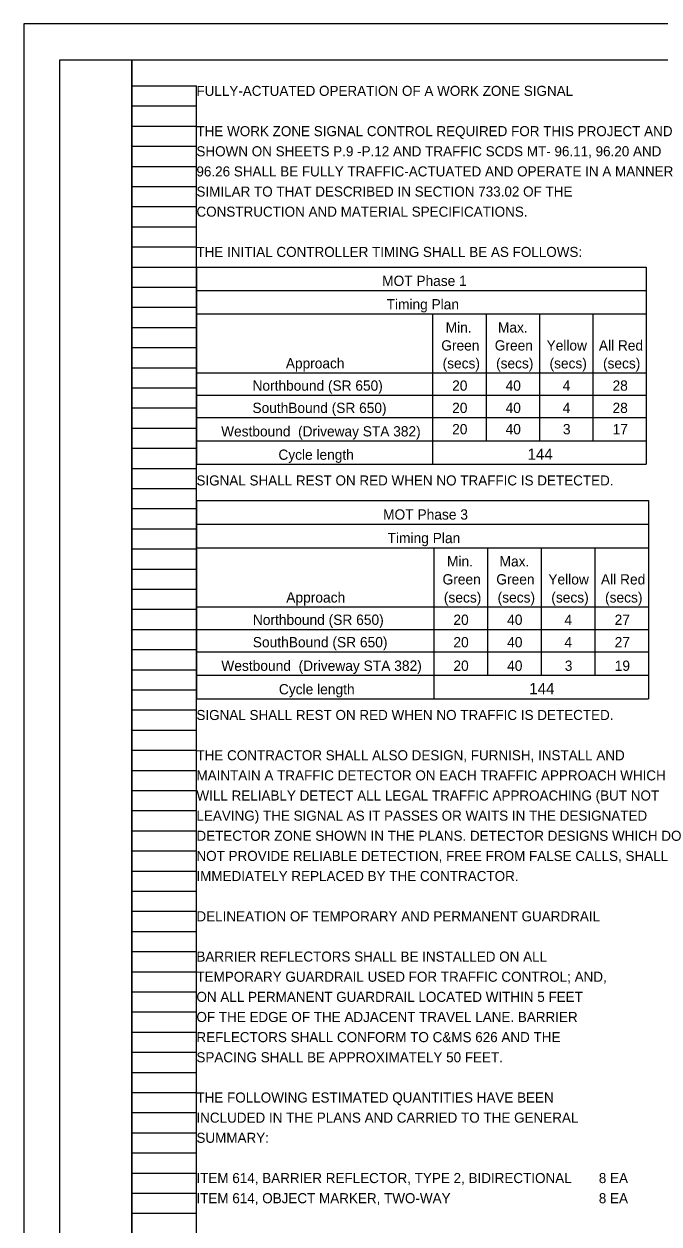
# Model space of a CAD drawing. Extents: x -18.6 to 34, y -8.1 to 37.1.
# Drawn here: x 0 to 8.84, y 5.31 to 22 of the extents above; entities that cross this region are included whole.
import ezdxf

# ---------------------------------------------------------------- set-up
doc = ezdxf.new("R2010")
doc.units = 0
for name, color, linetype in [('AP_P_Text', 7, 'Continuous'), ('Default', 7, 'Continuous'), ('SH_Border', 7, 'Continuous'), ('SH_Cut_Line', 7, 'Continuous'), ('SH_Data', 7, 'Continuous'), ('SH_Text', 7, 'Continuous')]:
    doc.layers.add(name, color=color, linetype=linetype)

msp = doc.modelspace()

# ---------------------------------------------------------------- linework, layer by layer
at = {"layer": 'AP_P_Text'}
for p, q in [((2.4, 18.62), (8.661, 18.62)), ((2.4, 18.62), (2.4, 15.877)), ((8.661, 18.62), (8.661, 15.877)), ((2.4, 18.295), (8.661, 18.295)), ((2.4, 17.969), (8.661, 17.969)), ((5.686, 17.969), (5.686, 15.877)), ((6.43, 17.969), (6.43, 16.202)), ((7.173, 17.969), (7.173, 16.202)), ((7.917, 17.969), (7.917, 16.202)), ((2.4, 17.148), (8.661, 17.148)), ((2.4, 16.838), (8.661, 16.838)), ((2.4, 16.528), (8.661, 16.528)), ((2.4, 16.202), (8.661, 16.202)), ((2.4, 15.877), (8.661, 15.877)), ((2.4, 15.372), (8.692, 15.372)), ((2.4, 15.372), (2.4, 12.615)), ((8.692, 15.372), (8.692, 12.615)), ((2.4, 15.044), (8.692, 15.044)), ((2.4, 14.717), (8.692, 14.717)), ((5.702, 14.717), (5.702, 12.615)), ((6.45, 14.717), (6.45, 12.942)), ((7.197, 14.717), (7.197, 12.942)), ((7.945, 14.717), (7.945, 12.942)), ((2.4, 13.892), (8.692, 13.892)), ((2.4, 13.58), (8.692, 13.58)), ((2.4, 13.269), (8.692, 13.269)), ((2.4, 12.942), (8.692, 12.942)), ((2.4, 12.615), (8.692, 12.615))]:
    msp.add_line(p, q, dxfattribs=at)
at = {"layer": 'SH_Border'}
for points in [[(0.5, 21.5), (1.5, 21.5), (1.5, 0.5), (0.5, 0.5)], [(1.5, 21.5), (33.5, 21.5), (33.5, 0.5), (1.5, 0.5)]]:
    msp.add_lwpolyline(points, close=True, dxfattribs=at)
at = {"layer": 'SH_Cut_Line'}
msp.add_lwpolyline([(0, 0), (34, 0), (34, 22), (0, 22)], close=True, dxfattribs=at)
at = {"layer": 'SH_Data'}
for p, q in [((1.5, 0.98), (1.5, 21.14)), ((1.5, 21.14), (2.4, 21.14)), ((2.4, 0.98), (2.4, 21.14)), ((1.5, 20.86), (2.4, 20.86)), ((1.5, 20.58), (2.4, 20.58)), ((1.5, 20.3), (2.4, 20.3)), ((1.5, 20.02), (2.4, 20.02)), ((1.5, 19.74), (2.4, 19.74)), ((1.5, 19.46), (2.4, 19.46)), ((1.5, 19.18), (2.4, 19.18)), ((1.5, 18.9), (2.4, 18.9)), ((1.5, 18.62), (2.4, 18.62)), ((1.5, 18.34), (2.4, 18.34)), ((1.5, 18.06), (2.4, 18.06)), ((1.5, 17.78), (2.4, 17.78)), ((1.5, 17.5), (2.4, 17.5)), ((1.5, 17.22), (2.4, 17.22)), ((1.5, 16.94), (2.4, 16.94)), ((1.5, 16.66), (2.4, 16.66)), ((1.5, 16.38), (2.4, 16.38)), ((1.5, 16.1), (2.4, 16.1)), ((1.5, 15.82), (2.4, 15.82)), ((1.5, 15.54), (2.4, 15.54)), ((1.5, 15.26), (2.4, 15.26)), ((1.5, 14.98), (2.4, 14.98)), ((1.5, 14.7), (2.4, 14.7)), ((1.5, 14.42), (2.4, 14.42)), ((1.5, 14.14), (2.4, 14.14)), ((1.5, 13.86), (2.4, 13.86)), ((1.5, 13.58), (2.4, 13.58)), ((1.5, 13.3), (2.4, 13.3)), ((1.5, 13.02), (2.4, 13.02)), ((1.5, 12.74), (2.4, 12.74)), ((1.5, 12.46), (2.4, 12.46)), ((1.5, 12.18), (2.4, 12.18)), ((1.5, 11.9), (2.4, 11.9)), ((1.5, 11.62), (2.4, 11.62)), ((1.5, 11.34), (2.4, 11.34)), ((1.5, 11.06), (2.4, 11.06)), ((1.5, 10.78), (2.4, 10.78)), ((1.5, 10.5), (2.4, 10.5)), ((1.5, 10.22), (2.4, 10.22)), ((1.5, 9.94), (2.4, 9.94)), ((1.5, 9.66), (2.4, 9.66)), ((1.5, 9.38), (2.4, 9.38)), ((1.5, 9.1), (2.4, 9.1)), ((1.5, 8.82), (2.4, 8.82)), ((1.5, 8.54), (2.4, 8.54)), ((1.5, 8.26), (2.4, 8.26)), ((1.5, 7.98), (2.4, 7.98)), ((1.5, 7.7), (2.4, 7.7)), ((1.5, 7.42), (2.4, 7.42)), ((1.5, 7.14), (2.4, 7.14)), ((1.5, 6.86), (2.4, 6.86)), ((1.5, 6.58), (2.4, 6.58)), ((1.5, 6.3), (2.4, 6.3)), ((1.5, 6.02), (2.4, 6.02)), ((1.5, 5.74), (2.4, 5.74)), ((1.5, 5.46), (2.4, 5.46))]:
    msp.add_line(p, q, dxfattribs=at)

# ---------------------------------------------------------------- texts
at = {"layer": 'AP_P_Text'}
for s, height, p in [('MOT Phase 1', 0.14258, (4.985, 18.357)), ('Timing Plan', 0.14258, (5.047, 18.031)), ('Min. ', 0.1426, (5.869, 17.709)), ('Max. ', 0.1426, (6.597, 17.709)), ('Green ', 0.1426, (5.808, 17.459)), ('Green', 0.1426, (6.552, 17.459)), ('Yellow ', 0.1426, (7.273, 17.459)), ('All Red ', 0.1426, (8.001, 17.459)), ('Approach', 0.1426, (3.644, 17.21)), ('(secs)', 0.1426, (5.826, 17.21)), ('(secs)', 0.1426, (6.57, 17.21)), ('(secs)', 0.1426, (7.314, 17.21)), ('(secs)', 0.1426, (8.058, 17.21)), ('Northbound (SR 650)', 0.14258, (3.181, 16.9)), ('20', 0.1426, (5.959, 16.9)), ('40', 0.1426, (6.703, 16.9)), ('4', 0.143, (7.497, 16.9)), ('28', 0.1426, (8.191, 16.9)), ('SouthBound (SR 650)', 0.14258, (3.18, 16.59)), ('20', 0.1426, (5.959, 16.59)), ('40', 0.1426, (6.703, 16.59)), ('4', 0.143, (7.497, 16.59)), ('28', 0.1426, (8.191, 16.59)), ('Westbound  (Driveway STA 382)', 0.14258, (2.744, 16.264)), ('20', 0.1426, (5.959, 16.294)), ('40', 0.1426, (6.703, 16.294)), ('3', 0.143, (7.5, 16.294)), ('17', 0.1426, (8.192, 16.294)), ('Cycle length', 0.14258, (3.541, 15.939)), ('144', 0.1568, (7.008, 15.939)), ('MOT Phase 3', 0.14329, (4.997, 15.107)), ('Timing Plan', 0.14329, (5.06, 14.78)), ('Min. ', 0.1433, (5.887, 14.456)), ('Max. ', 0.1433, (6.618, 14.456)), ('Yellow ', 0.1433, (7.297, 14.205)), ('All Red ', 0.1433, (8.029, 14.205)), ('Green ', 0.1433, (5.825, 14.205)), ('Green', 0.1433, (6.573, 14.205)), ('Approach', 0.1433, (3.65, 13.954)), ('(secs)', 0.1433, (5.843, 13.954)), ('(secs)', 0.1433, (6.591, 13.954)), ('(secs)', 0.1433, (7.338, 13.954)), ('(secs)', 0.1433, (8.086, 13.954)), ('Northbound (SR 650)', 0.14329, (3.185, 13.643)), ('20', 0.1433, (5.976, 13.643)), ('40', 0.1433, (6.724, 13.643)), ('4', 0.143, (7.522, 13.643)), ('27', 0.1433, (8.22, 13.643)), ('SouthBound (SR 650)', 0.14329, (3.184, 13.331)), ('20', 0.1433, (5.976, 13.331)), ('40', 0.1433, (6.724, 13.331)), ('4', 0.143, (7.522, 13.331)), ('27', 0.1433, (8.22, 13.331)), ('Westbound  (Driveway STA 382)', 0.14329, (2.746, 13.004)), ('20', 0.1433, (5.976, 13.004)), ('40', 0.1433, (6.724, 13.004)), ('3', 0.143, (7.526, 13.004)), ('19', 0.1433, (8.221, 13.004)), ('Cycle length', 0.14329, (3.547, 12.677)), ('144', 0.1576, (7.031, 12.677))]:
    msp.add_text(s, height=height, dxfattribs=at).set_placement(p)
at = {"layer": 'Default'}
for s, p in [('FULLY-ACTUATED OPERATION OF A WORK ZONE SIGNAL', (2.4, 21)), ('THE WORK ZONE SIGNAL CONTROL REQUIRED FOR THIS PROJECT AND ', (2.4, 20.44)), ('SHOWN ON SHEETS P.9 -P.12 AND TRAFFIC SCDS MT- 96.11, 96.20 AND ', (2.4, 20.16)), ('96.26 SHALL BE FULLY TRAFFIC-ACTUATED AND OPERATE IN A MANNER ', (2.4, 19.88)), ('SIMILAR TO THAT DESCRIBED IN SECTION 733.02 OF THE ', (2.4, 19.6)), ('CONSTRUCTION AND MATERIAL SPECIFICATIONS.', (2.4, 19.32)), ('THE INITIAL CONTROLLER TIMING SHALL BE AS FOLLOWS:', (2.4, 18.76)), ('THE CONTRACTOR SHALL ALSO DESIGN, FURNISH, INSTALL AND ', (2.4, 11.76)), ('MAINTAIN A TRAFFIC DETECTOR ON EACH TRAFFIC APPROACH WHICH ', (2.4, 11.48)), ('WILL RELIABLY DETECT ALL LEGAL TRAFFIC APPROACHING (BUT NOT ', (2.4, 11.2)), ('LEAVING) THE SIGNAL AS IT PASSES OR WAITS IN THE DESIGNATED ', (2.4, 10.92)), ('DETECTOR ZONE SHOWN IN THE PLANS. DETECTOR DESIGNS WHICH DO ', (2.4, 10.64)), ('NOT PROVIDE RELIABLE DETECTION, FREE FROM FALSE CALLS, SHALL BE ', (2.4, 10.36)), ('IMMEDIATELY REPLACED BY THE CONTRACTOR. ', (2.4, 10.08))]:
    msp.add_text(s, height=0.14, dxfattribs=at).set_placement(p)
at = {"layer": 'SH_Text'}
for s, p in [('SIGNAL SHALL REST ON RED WHEN NO TRAFFIC IS DETECTED.', (2.4, 15.582)), ('SIGNAL SHALL REST ON RED WHEN NO TRAFFIC IS DETECTED.', (2.4, 12.32)), ('DELINEATION OF TEMPORARY AND PERMANENT GUARDRAIL', (2.4, 9.52)), ('BARRIER REFLECTORS SHALL BE INSTALLED ON ALL', (2.4, 8.96)), ('TEMPORARY GUARDRAIL USED FOR TRAFFIC CONTROL; AND,', (2.4, 8.68)), ('ON ALL PERMANENT GUARDRAIL LOCATED WITHIN 5 FEET', (2.4, 8.4)), ('OF THE EDGE OF THE ADJACENT TRAVEL LANE. BARRIER', (2.4, 8.12)), ('REFLECTORS SHALL CONFORM TO C&MS 626 AND THE', (2.4, 7.84)), ('SPACING SHALL BE APPROXIMATELY 50 FEET.', (2.4, 7.56)), ('THE FOLLOWING ESTIMATED QUANTITIES HAVE BEEN', (2.4, 7)), ('INCLUDED IN THE PLANS AND CARRIED TO THE GENERAL', (2.4, 6.72)), ('SUMMARY:', (2.4, 6.44)), ('ITEM 614, BARRIER REFLECTOR, TYPE 2, BIDIRECTIONAL', (2.4, 5.88)), ('8 EA', (8, 5.88)), ('ITEM 614, OBJECT MARKER, TWO-WAY  ', (2.4, 5.6)), ('8 EA', (8, 5.6))]:
    msp.add_text(s, height=0.14, dxfattribs=at).set_placement(p)

doc.saveas('drawing.dxf')
